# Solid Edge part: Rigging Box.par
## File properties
Author: m_hel
Template: Iso Metric Part.par
Last saved by: m_hel
Revision: 2
Application: Solid Edge
Username: m_hel
Accuracy: 0,990
Material: Glass Fiber
Face Style: White (dull)
Fill Style: ANSI36(Marble)
Virtual Style: ANSI36(Marble)
Grouping: Uncategorized
LibraryName: Custom Materials
Coef. of Thermal Exp: 0.0
Thermal Conductivity: 0.0
Specific Heat: 0.0
Modulus of Elasticity: 0.0
Poisson's Ratio: 0.0
Yield Stress: 0.0
Ultimate Stress: 0.0
Elongation: 0.0
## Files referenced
..\..\Redfisher18.asm
G:\OneDriveTemp\OneDrive\Dokumendid\TLÜ tööd\3D Modelleerimine\3d modelling\veesõiduk\Deck1.par
iduk\Deck1.par
iduk\Redfisher18.asm
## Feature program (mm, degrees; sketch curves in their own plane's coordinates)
sketch for "unnamed Protrusion 1" plane through (0, 0, 0) normal (0, 0, 1) x-axis (1, 0, 0)
  line (-10, -870) -> (370, -870)
  arc centre (370, -860) radius 10 from (380, -860) to (370, -870) cw
  line (380, -860) -> (380, 20)
  arc centre (370, 20) radius 10 from (380, 20) to (370, 30) ccw
  line (370, 30) -> (-10, 30)
  arc centre (-10, 20) radius 10 from (-10, 30) to (-20, 20) ccw
  line (-20, 20) -> (-20, -860)
  arc centre (-10, -860) radius 10 from (-10, -870) to (-20, -860) cw
extrude "unnamed Protrusion 1" add finite 200 along -normal
thinwall "Thinwall_1"  Thickness = 50 mm
thinwall "Thinwall_2"  Thickness = 20 mm
fillet "Round_1" radius 30
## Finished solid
Body 1: solid body, 44 faces, 96 edges, 56 vertices.
  Faces by surface: cylinder 20, plane 16, blend 4, sphere 4
  Edges by curve: line 56, circle 32, ellipse 8
Bounding box of the edges (mm; curved faces can reach further): 500.000 x 1000.000 x 220.000, from (-70, -920, -220) to (430, 80, 0).
Cylindrical faces by radius (mm): R10 x4, R30 x12, R60 x4
Spherical faces by radius (mm): R30 x4
Planar faces by outward normal: +x 3, +y 3, +z 2, -x 3, -y 3, -z 2
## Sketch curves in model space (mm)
arc centre (-10, -860, 0) radius 10 from (-10, -870, 0) through (-17.2737, -866.8624, 0) to (-20, -860, 0)
line (-10, -870, 0) -> (370, -870, 0)
arc centre (370, -860, 0) radius 10 from (380, -860, 0) through (376.8624, -867.2737, 0) to (370, -870, 0)
line (380, -860, 0) -> (380, 20, 0)
arc centre (370, 20, 0) radius 10 from (380, 20, 0) through (376.8624, 27.2737, 0) to (370, 30, 0)
line (370, 30, 0) -> (-10, 30, 0)
arc centre (-10, 20, 0) radius 10 from (-10, 30, 0) through (-17.2737, 26.8624, 0) to (-20, 20, 0)
line (-20, 20, 0) -> (-20, -860, 0)
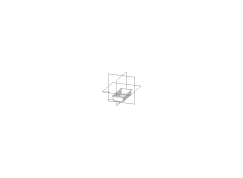
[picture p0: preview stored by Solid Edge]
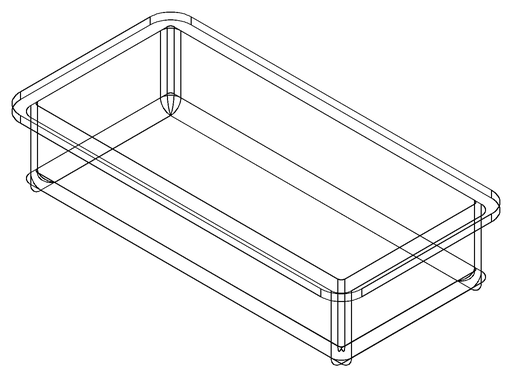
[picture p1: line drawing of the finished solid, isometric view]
